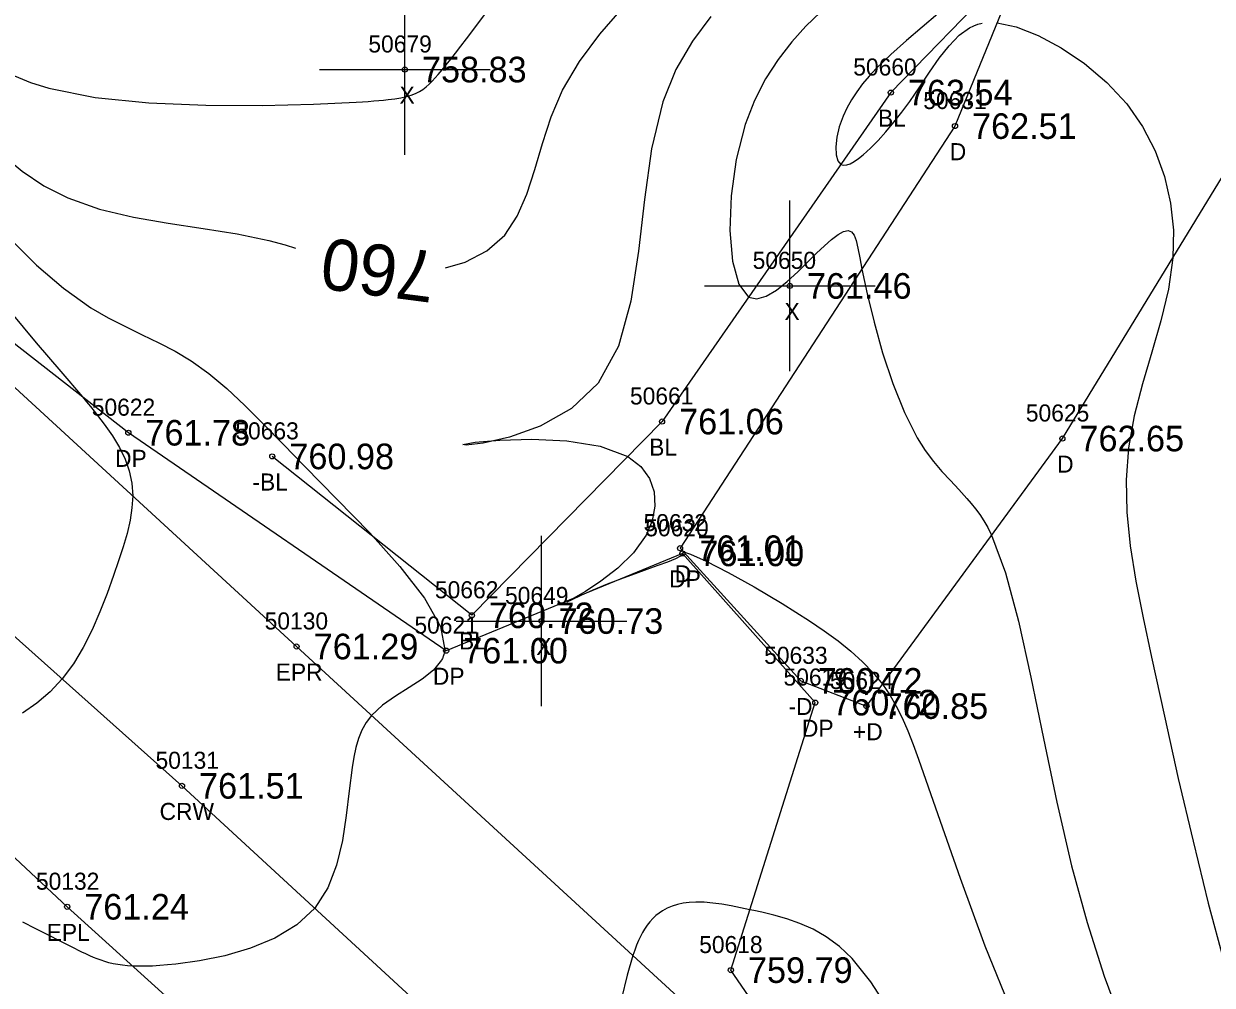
# Model space of a CAD drawing. Extents: x 1378535 to 1380697, y 997729 to 1000024.
# Drawn here: x 1379102.8 to 1379172.5, y 999468.2 to 999524.5 of the extents above; entities that cross this region are included whole.
import ezdxf

# ---------------------------------------------------------------- set-up
doc = ezdxf.new("R2010")
doc.units = 0
for name, color, linetype in [('RD_DTM_BkLn1', 7, 'Continuous'), ('RD_DTM_BkLn_txCode', 7, 'Continuous'), ('RD_DTM_Major1', 7, 'Continuous'), ('RD_DTM_Major1_Lbl', 7, 'Continuous'), ('RD_DTM_Minor1', 7, 'Continuous'), ('RD_EX_Driveway', 7, 'Continuous'), ('RD_EX_Driveway_txCode', 7, 'Continuous'), ('RD_EX_Misc', 7, 'Continuous'), ('RD_EX_Misc_txCode', 7, 'Continuous'), ('RD_EX_Road', 7, 'Continuous'), ('RD_EX_Road_txCode', 7, 'Continuous'), ('RD_EX_TX_Driveway_ELEV', 7, 'Continuous'), ('RD_EX_TX_Misc_ELEV', 7, 'Continuous'), ('RD_EX_TX_Road_ELEV', 7, 'Continuous'), ('RD_HC_Survey_ELEV', 7, 'Continuous'), ('RD_HC_Survey_txCode', 7, 'Continuous'), ('RD_SMD_Locator', 7, 'Continuous')]:
    doc.layers.add(name, color=color, linetype=linetype)

msp = doc.modelspace()

# ---------------------------------------------------------------- linework, layer by layer
at = {"layer": 'RD_DTM_BkLn1'}
for points in [[(1379201.7, 999398.205), (1379156.533, 999438.891), (1379112.084, 999479.847), (1379066.495, 999520.561), (1379020.821, 999562.613), (1378974.239, 999604.981), (1378928.957, 999646.778), (1378882.739, 999688.619), (1378834.578, 999733.071), (1378787.698, 999775.121), (1378743.642, 999816.274), (1378698.706, 999856.431), (1378652.056, 999898.787), (1378607.023, 999939.646), (1378604.538, 999941.267)], [(1379169.71, 999558.631), (1379159.951, 999527.011), (1379153.64, 999520.496), (1379140.228, 999501.207), (1379129.077, 999489.845), (1379117.378, 999499.162)]]:
    msp.add_lwpolyline(points, dxfattribs=at)
at = {"layer": 'RD_DTM_Major1'}
for points in [[(1379095.703, 999525.287), (1379096.377, 999524.226), (1379096.791, 999523.529), (1379097.186, 999522.838), (1379097.574, 999522.15), (1379097.967, 999521.465), (1379098.377, 999520.782), (1379098.816, 999520.097), (1379099.615, 999518.981), (1379100.526, 999517.887), (1379101.555, 999516.845), (1379102.707, 999515.884), (1379103.987, 999515.032), (1379105.401, 999514.317), (1379107.251, 999513.669), (1379109.232, 999513.194), (1379111.28, 999512.833), (1379113.329, 999512.525), (1379115.314, 999512.209), (1379117.17, 999511.824), (1379118.141, 999511.559), (1379118.748, 999511.369)], [(1379127.54, 999510.227), (1379128.691, 999510.555), (1379129.96, 999511.212), (1379131.003, 999512.138), (1379131.734, 999513.243), (1379132.294, 999514.543), (1379132.762, 999515.985), (1379133.216, 999517.515), (1379133.734, 999519.081), (1379134.394, 999520.63), (1379135.387, 999522.317), (1379136.578, 999523.917), (1379137.881, 999525.431)], [(1379153.543, 999466.688), (1379152.47, 999468.347), (1379151.372, 999469.72), (1379150.622, 999470.428), (1379149.853, 999470.994), (1379149.076, 999471.439), (1379148.3, 999471.785), (1379147.533, 999472.052), (1379146.785, 999472.263), (1379146.547, 999472.323), (1379146.311, 999472.38), (1379146.077, 999472.434), (1379145.612, 999472.537), (1379145.38, 999472.587), (1379144.827, 999472.703), (1379144.276, 999472.81), (1379143.731, 999472.903), (1379143.2, 999472.974), (1379142.687, 999473.018), (1379142.199, 999473.027), (1379141.825, 999473.006), (1379141.472, 999472.959), (1379141.138, 999472.886), (1379140.826, 999472.788), (1379140.533, 999472.666), (1379140.262, 999472.521), (1379140.059, 999472.387), (1379139.868, 999472.236), (1379139.688, 999472.068), (1379139.518, 999471.881), (1379139.357, 999471.674), (1379139.203, 999471.446), (1379139.081, 999471.241), (1379138.962, 999471.019), (1379138.847, 999470.777), (1379138.734, 999470.512), (1379138.623, 999470.222), (1379138.514, 999469.904), (1379138.181, 999468.746), (1379137.848, 999467.379)]]:
    msp.add_lwpolyline(points, dxfattribs=at)
at = {"layer": 'RD_DTM_Minor1'}
for points in [[(1379102.262, 999521.483), (1379103.205, 999521.09), (1379104.273, 999520.75), (1379107.002, 999520.208), (1379110.149, 999519.89), (1379113.485, 999519.749), (1379116.776, 999519.741), (1379119.791, 999519.819), (1379122.3, 999519.939), (1379122.661, 999519.961), (1379123.002, 999519.982), (1379123.322, 999520.005), (1379123.623, 999520.029), (1379123.905, 999520.054), (1379124.169, 999520.082), (1379124.567, 999520.133), (1379124.922, 999520.193), (1379125.239, 999520.264), (1379125.523, 999520.347), (1379125.778, 999520.446), (1379126.009, 999520.561), (1379126.206, 999520.684), (1379126.392, 999520.824), (1379126.57, 999520.981), (1379126.746, 999521.157), (1379126.924, 999521.351), (1379127.109, 999521.565), (1379127.334, 999521.833), (1379127.575, 999522.13), (1379127.836, 999522.457), (1379128.119, 999522.816), (1379128.425, 999523.211), (1379128.757, 999523.643), (1379129.83, 999525.068)], [(1379149.507, 999525.214), (1379148.664, 999524.391), (1379147.831, 999523.469), (1379147.032, 999522.439), (1379146.293, 999521.293), (1379145.638, 999520.023), (1379145.092, 999518.619), (1379144.569, 999516.57), (1379144.277, 999514.441), (1379144.209, 999512.401), (1379144.362, 999510.619), (1379144.728, 999509.264), (1379145.303, 999508.506), (1379145.787, 999508.395), (1379146.337, 999508.55), (1379146.933, 999508.91), (1379147.555, 999509.412), (1379148.18, 999509.993), (1379149.284, 999511.078), (1379149.745, 999511.513), (1379150.167, 999511.881), (1379150.542, 999512.165), (1379150.864, 999512.347), (1379151.128, 999512.409), (1379151.329, 999512.34), (1379151.483, 999512.14), (1379151.604, 999511.816), (1379151.71, 999511.372), (1379151.817, 999510.814), (1379151.941, 999510.148), (1379152.245, 999508.701), (1379152.654, 999507.027), (1379153.159, 999505.236), (1379153.754, 999503.436), (1379154.432, 999501.737), (1379155.186, 999500.247), (1379155.655, 999499.513), (1379156.141, 999498.866), (1379156.634, 999498.282), (1379157.13, 999497.741), (1379157.619, 999497.221), (1379158.095, 999496.701), (1379158.353, 999496.402), (1379158.604, 999496.088), (1379158.849, 999495.753), (1379159.087, 999495.388), (1379159.319, 999494.986), (1379159.544, 999494.541), (1379160.366, 999492.339), (1379161.124, 999489.51), (1379161.854, 999486.218), (1379162.592, 999482.621), (1379163.374, 999478.882), (1379164.236, 999475.162), (1379165.141, 999471.827), (1379166.139, 999468.689), (1379167.225, 999465.788)], [(1379156.39, 999525.121), (1379155.484, 999524.331), (1379154.552, 999523.54), (1379153.638, 999522.738), (1379152.786, 999521.915), (1379152.369, 999521.463), (1379151.986, 999521.002), (1379151.638, 999520.536), (1379151.33, 999520.064), (1379151.063, 999519.589), (1379150.841, 999519.111), (1379150.619, 999518.479), (1379150.479, 999517.873), (1379150.42, 999517.322), (1379150.44, 999516.854), (1379150.538, 999516.5), (1379150.713, 999516.287), (1379150.868, 999516.235), (1379151.052, 999516.25), (1379151.262, 999516.326), (1379151.496, 999516.456), (1379151.751, 999516.634), (1379152.023, 999516.854), (1379152.445, 999517.238), (1379152.89, 999517.689), (1379153.351, 999518.196), (1379153.819, 999518.752), (1379154.287, 999519.346), (1379154.745, 999519.97), (1379155.338, 999520.833), (1379155.912, 999521.693), (1379156.479, 999522.51), (1379157.052, 999523.243), (1379157.641, 999523.854), (1379158.259, 999524.301), (1379158.497, 999524.417), (1379158.744, 999524.506), (1379159.002, 999524.567)], [(1379143.089, 999524.954), (1379142.003, 999523.505), (1379141.04, 999521.845), (1379140.267, 999519.96), (1379139.603, 999517.207), (1379139.188, 999514.226), (1379138.845, 999511.189), (1379138.397, 999508.267), (1379137.668, 999505.63), (1379136.479, 999503.45), (1379134.914, 999501.972), (1379133.09, 999500.943), (1379131.274, 999500.291), (1379129.733, 999499.942), (1379128.736, 999499.826), (1379128.549, 999499.871), (1379129.28, 999499.992), (1379130.713, 999500.118), (1379132.586, 999500.173), (1379134.636, 999500.081), (1379136.601, 999499.768), (1379138.218, 999499.159), (1379138.973, 999498.578), (1379139.482, 999497.874), (1379139.756, 999497.083), (1379139.807, 999496.241), (1379139.647, 999495.383), (1379139.288, 999494.543), (1379138.553, 999493.519), (1379137.627, 999492.612), (1379136.642, 999491.846), (1379135.73, 999491.245), (1379135.022, 999490.833), (1379134.649, 999490.635), (1379134.668, 999490.642), (1379134.96, 999490.78), (1379135.479, 999491.02), (1379136.182, 999491.332), (1379137.023, 999491.686), (1379137.958, 999492.051), (1379138.662, 999492.307), (1379139.356, 999492.55), (1379140.005, 999492.778), (1379140.575, 999492.987), (1379141.031, 999493.175), (1379141.337, 999493.339), (1379141.387, 999493.377), (1379141.408, 999493.395), (1379141.425, 999493.413), (1379141.438, 999493.43), (1379141.449, 999493.447), (1379141.453, 999493.456), (1379141.458, 999493.469), (1379141.459, 999493.474), (1379141.463, 999493.494), (1379141.464, 999493.513), (1379141.464, 999493.53), (1379141.466, 999493.544), (1379141.471, 999493.555), (1379141.481, 999493.562), (1379141.9, 999493.441), (1379142.818, 999493.018), (1379144.106, 999492.353), (1379145.632, 999491.508), (1379147.266, 999490.544), (1379148.879, 999489.522), (1379149.738, 999488.936), (1379150.544, 999488.345), (1379151.292, 999487.743), (1379151.978, 999487.123), (1379152.599, 999486.479), (1379153.15, 999485.805), (1379153.574, 999485.184), (1379153.953, 999484.528), (1379154.3, 999483.83), (1379154.626, 999483.082), (1379154.943, 999482.278), (1379155.264, 999481.411), (1379156.401, 999478.17), (1379157.698, 999474.437), (1379159.153, 999470.457), (1379160.764, 999466.476)], [(1379159.871, 999524.587), (1379160.991, 999524.343), (1379162.267, 999523.847), (1379163.625, 999523.124), (1379164.993, 999522.197), (1379166.297, 999521.091), (1379167.464, 999519.829), (1379168.395, 999518.503), (1379169.134, 999517.078), (1379169.682, 999515.576), (1379170.038, 999514.017), (1379170.201, 999512.422), (1379170.171, 999510.811), (1379169.911, 999508.963), (1379169.475, 999507.117), (1379168.943, 999505.269), (1379168.395, 999503.415), (1379167.909, 999501.548), (1379167.567, 999499.664), (1379167.43, 999497.797), (1379167.477, 999495.887), (1379167.678, 999493.913), (1379168.005, 999491.854), (1379168.427, 999489.689), (1379168.916, 999487.395), (1379169.673, 999483.928), (1379170.49, 999480.286), (1379171.353, 999476.595), (1379172.249, 999472.977), (1379173.163, 999469.559)], [(1379102.022, 999511.91), (1379103.552, 999510.386), (1379105.14, 999509.024), (1379106.745, 999507.883), (1379107.76, 999507.288), (1379108.764, 999506.772), (1379109.754, 999506.297), (1379110.728, 999505.829), (1379111.685, 999505.332), (1379112.622, 999504.77), (1379113.666, 999504.018), (1379114.706, 999503.143), (1379115.765, 999502.155), (1379116.865, 999501.059), (1379118.03, 999499.864), (1379119.283, 999498.576), (1379121.168, 999496.664), (1379123.087, 999494.679), (1379124.859, 999492.712), (1379126.305, 999490.854), (1379127.245, 999489.193), (1379127.499, 999487.821), (1379127.489, 999487.753), (1379127.476, 999487.686), (1379127.461, 999487.621), (1379127.443, 999487.557), (1379127.422, 999487.493), (1379127.399, 999487.431), (1379127.384, 999487.393), (1379127.367, 999487.356), (1379127.35, 999487.319), (1379127.313, 999487.246), (1379127.293, 999487.21), (1379126.822, 999486.627), (1379126.168, 999486.105), (1379125.405, 999485.612), (1379124.606, 999485.115), (1379123.846, 999484.581), (1379123.2, 999483.978), (1379122.886, 999483.561), (1379122.634, 999483.106), (1379122.435, 999482.614), (1379122.278, 999482.086), (1379122.154, 999481.523), (1379122.054, 999480.926), (1379121.884, 999479.564), (1379121.717, 999478.114), (1379121.492, 999476.638), (1379121.149, 999475.199), (1379120.627, 999473.858), (1379119.864, 999472.679), (1379118.81, 999471.699), (1379117.529, 999470.923), (1379116.099, 999470.328), (1379114.601, 999469.89), (1379113.114, 999469.586), (1379111.718, 999469.392), (1379111.236, 999469.343), (1379110.779, 999469.307), (1379110.346, 999469.281), (1379109.939, 999469.268), (1379109.557, 999469.266), (1379109.201, 999469.276), (1379108.888, 999469.295), (1379108.595, 999469.325), (1379108.319, 999469.364), (1379108.056, 999469.415), (1379107.804, 999469.475), (1379107.558, 999469.546), (1379107.338, 999469.619), (1379107.119, 999469.701), (1379106.899, 999469.791), (1379106.676, 999469.888), (1379106.448, 999469.992), (1379106.215, 999470.103), (1379105.605, 999470.403), (1379104.95, 999470.736), (1379104.254, 999471.093), (1379103.518, 999471.47), (1379102.748, 999471.858)], [(1379102.008, 999507.661), (1379103.544, 999505.822), (1379104.988, 999504.133), (1379106.251, 999502.65), (1379106.49, 999502.364), (1379106.717, 999502.088), (1379106.933, 999501.822), (1379107.138, 999501.563), (1379107.334, 999501.31), (1379107.521, 999501.062), (1379108.005, 999500.37), (1379108.416, 999499.689), (1379108.748, 999499.008), (1379108.993, 999498.316), (1379109.144, 999497.602), (1379109.195, 999496.854), (1379109.153, 999496.151), (1379109.038, 999495.416), (1379108.861, 999494.65), (1379108.634, 999493.855), (1379108.368, 999493.034), (1379108.076, 999492.189), (1379107.691, 999491.123), (1379107.273, 999490.048), (1379106.811, 999488.987), (1379106.295, 999487.963), (1379105.715, 999486.999), (1379105.06, 999486.12), (1379104.347, 999485.362), (1379103.569, 999484.694), (1379102.743, 999484.104)]]:
    msp.add_lwpolyline(points, dxfattribs=at)
at = {"layer": 'RD_EX_Driveway'}
for points in [[(1379175.357, 999565.121), (1379168.332, 999545.317), (1379157.399, 999518.53), (1379141.282, 999493.781), (1379148.356, 999486.001)], [(1379148.356, 999486.001), (1379152.21, 999484.521), (1379163.694, 999500.21), (1379176.205, 999520.688), (1379180.998, 999538.621), (1379185.943, 999560.405)], [(1379151.914, 999457.896), (1379144.262, 999469.042), (1379149.206, 999484.725), (1379141.421, 999493.478), (1379127.57, 999487.772), (1379108.939, 999500.55), (1379095.006, 999511.434)]]:
    msp.add_lwpolyline(points, dxfattribs=at)
at = {"layer": 'RD_EX_Misc'}
for p, q in [((1379125.152, 999516.846), (1379125.152, 999526.846)), ((1379120.152, 999521.846), (1379130.152, 999521.846)), ((1379147.719, 999504.16), (1379147.719, 999514.16)), ((1379142.719, 999509.16), (1379152.719, 999509.16)), ((1379133.163, 999484.51), (1379133.163, 999494.51)), ((1379128.163, 999489.51), (1379138.163, 999489.51))]:
    msp.add_line(p, q, dxfattribs=at)
at = {"layer": 'RD_EX_Road'}
for points in [[(1379209.475, 999405.54), (1379163.997, 999446.485), (1379118.805, 999488.017), (1379074.408, 999528.841), (1379028.669, 999569.9), (1378981.979, 999612.718), (1378937.166, 999653.911), (1378890.129, 999696.785), (1378842.566, 999740.72), (1378794.879, 999783.075), (1378749.806, 999824.149), (1378706.231, 999863.66), (1378659.579, 999905.32), (1378614.058, 999947.757), (1378610.306, 999950.384)], [(1379194.921, 999391.17), (1379151.382, 999431.093), (1379105.356, 999472.756), (1379062.213, 999513.117), (1379014.238, 999555.894), (1378967.91, 999597.354), (1378922.421, 999639.979), (1378876.774, 999681.523), (1378827.896, 999726.217), (1378781.196, 999768.463), (1378736.445, 999808.724), (1378691.95, 999849.175), (1378644.395, 999891.391), (1378600.504, 999932.423), (1378598.568, 999933.73)]]:
    msp.add_lwpolyline(points, dxfattribs=at)
at = {"layer": 'RD_SMD_Locator'}
for centre in [(1379125.152, 999521.846), (1379153.64, 999520.496), (1379157.399, 999518.53), (1379147.719, 999509.16), (1379140.228, 999501.207), (1379108.939, 999500.55), (1379163.694, 999500.21), (1379117.378, 999499.162), (1379141.282, 999493.781), (1379141.421, 999493.478), (1379129.077, 999489.845), (1379133.163, 999489.51), (1379118.805, 999488.017), (1379127.57, 999487.772), (1379148.356, 999486.001), (1379149.206, 999484.725), (1379152.21, 999484.521), (1379112.084, 999479.847), (1379105.356, 999472.756), (1379144.262, 999469.042)]:
    msp.add_circle(centre, 0.15, dxfattribs=at)

# ---------------------------------------------------------------- texts
at = {"layer": 'RD_DTM_BkLn_txCode'}
for s, p in [('50660', (1379151.435, 999521.496)), ('BL', (1379152.884, 999518.496)), ('50661', (1379138.346, 999502.207)), ('50663', (1379115.213, 999500.162)), ('BL', (1379139.472, 999499.207)), ('-BL', (1379116.213, 999497.162)), ('50662', (1379126.912, 999490.845)), ('BL', (1379128.321, 999487.845))]:
    msp.add_text(s, height=1, dxfattribs=at).set_placement(p)
at = {"layer": 'RD_DTM_Major1_Lbl'}
msp.add_text('760', height=3, rotation=172.60066, dxfattribs=at).set_placement((1379127.108, 999511.139))
at = {"layer": 'RD_EX_Driveway_txCode'}
for s, p in [('50631', (1379155.541, 999519.53)), ('D', (1379157.092, 999516.53)), ('50622', (1379106.797, 999501.55)), ('50625', (1379161.552, 999501.21)), ('DP', (1379108.159, 999498.55)), ('D', (1379163.387, 999498.21)), ('50632', (1379139.14, 999494.781)), ('50620', (1379139.24, 999494.478)), ('DP', (1379140.642, 999491.478)), ('D', (1379140.975, 999491.781)), ('50621', (1379125.712, 999488.772)), ('50633', (1379146.214, 999487.001)), ('DP', (1379126.79, 999485.772)), ('50619', (1379147.348, 999485.725)), ('50624', (1379150.068, 999485.521)), ('-D', (1379147.639, 999484.001)), ('DP', (1379148.426, 999482.725)), ('+D', (1379151.415, 999482.521)), ('50618', (1379142.404, 999470.042))]:
    msp.add_text(s, height=1, dxfattribs=at).set_placement(p)
at = {"layer": 'RD_EX_Misc_txCode'}
for s, p in [('50679', (1379123.01, 999522.846)), ('X', (1379124.837, 999519.846)), ('50650', (1379145.538, 999510.16)), ('X', (1379147.404, 999507.16)), ('50649', (1379131.021, 999490.51)), ('X', (1379132.848, 999487.51))]:
    msp.add_text(s, height=1, dxfattribs=at).set_placement(p)
at = {"layer": 'RD_EX_Road_txCode'}
for s, p in [('50130', (1379116.931, 999489.017)), ('EPR', (1379117.577, 999486.017)), ('50132', (1379103.521, 999473.756)), ('EPL', (1379104.151, 999470.756))]:
    msp.add_text(s, height=1, dxfattribs=at).set_placement(p)
at = {"layer": 'RD_EX_TX_Driveway_ELEV'}
for s, p in [('762.51', (1379158.399, 999517.78)), ('761.78', (1379109.939, 999499.8)), ('762.65', (1379164.694, 999499.46)), ('761.01', (1379142.282, 999493.031)), ('761.00', (1379142.421, 999492.728)), ('761.00', (1379128.57, 999487.022)), ('760.72', (1379149.356, 999485.251)), ('760.72', (1379150.206, 999483.975)), ('760.85', (1379153.21, 999483.771)), ('759.79', (1379145.262, 999468.292))]:
    msp.add_text(s, height=1.5, dxfattribs=at).set_placement(p)
at = {"layer": 'RD_EX_TX_Misc_ELEV'}
for s, p in [('758.83', (1379126.152, 999521.096)), ('763.54', (1379154.64, 999519.746)), ('761.46', (1379148.719, 999508.41)), ('761.06', (1379141.228, 999500.457)), ('760.98', (1379118.378, 999498.412)), ('760.72', (1379130.077, 999489.095)), ('760.73', (1379134.163, 999488.76))]:
    msp.add_text(s, height=1.5, dxfattribs=at).set_placement(p)
at = {"layer": 'RD_EX_TX_Road_ELEV'}
for s, p in [('761.29', (1379119.805, 999487.267)), ('761.24', (1379106.356, 999472.006))]:
    msp.add_text(s, height=1.5, dxfattribs=at).set_placement(p)
at = {"layer": 'RD_HC_Survey_ELEV'}
msp.add_text('761.51', height=1.5, dxfattribs=at).set_placement((1379113.084, 999479.097))
at = {"layer": 'RD_HC_Survey_txCode'}
for s, p in [('50131', (1379110.533, 999480.847)), ('CRW', (1379110.769, 999477.847))]:
    msp.add_text(s, height=1, dxfattribs=at).set_placement(p)

doc.saveas('drawing.dxf')
